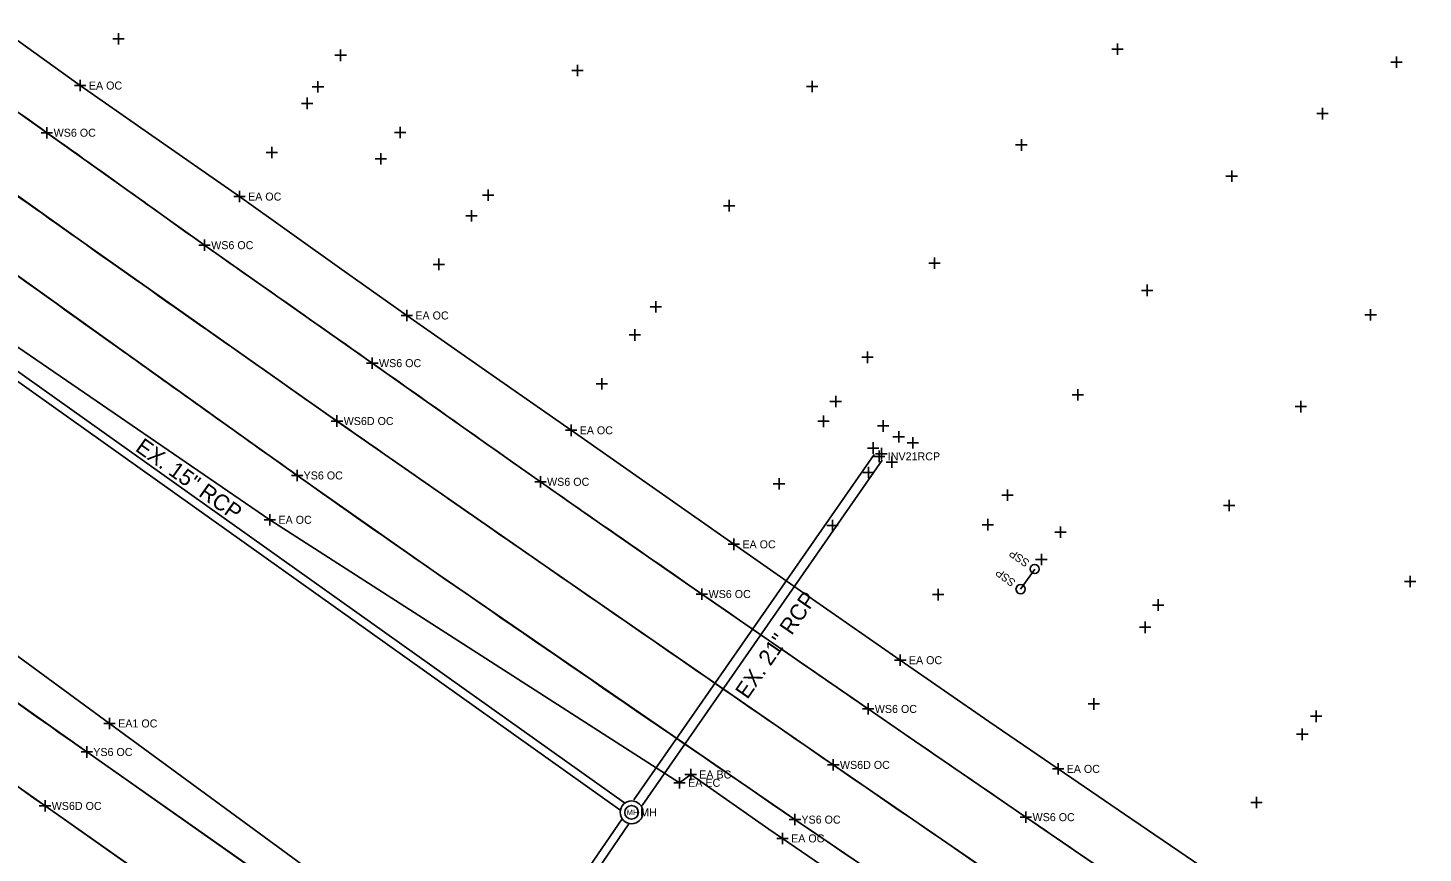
# Model space of a CAD drawing. Extents: x 1324236 to 1326110, y 459090 to 460782.
# Drawn here: x 1325338.7 to 1325582.8, y 459844.3 to 459988.7 of the extents above; entities that cross this region are included whole.
import ezdxf

# ---------------------------------------------------------------- set-up
doc = ezdxf.new("R2010")
doc.units = 0
for name, color, linetype in [('BD_X_Canopy', 7, 'Continuous'), ('DR_X_Ditch', 7, 'Continuous'), ('DT_X_Contour_Minor', 7, 'Continuous'), ('DT_X_Void', 7, 'Continuous'), ('DV_X_Property_Line', 7, 'Continuous'), ('LT_X_Poles', 7, 'Continuous'), ('PM_X_Edge_Line', 7, 'Continuous'), ('PM_X_Lane_Line', 7, 'Continuous'), ('PV_X_Shoulder', 7, 'Continuous'), ('RD_X_Concrete_Barrier', 7, 'Continuous'), ('RW_X_CL', 7, 'Continuous'), ('UT_X_Telecom', 7, 'Continuous'), ('VG_X_Flower_Bed', 7, 'Continuous')]:
    doc.layers.add(name, color=color, linetype=linetype)

msp = doc.modelspace()

# ---------------------------------------------------------------- linework, layer by layer
at = {"layer": 'BD_X_Canopy'}
for points in [[(1325307.55, 459980.26), (1325347.49, 459951.8), (1325347.49, 459951.8), (1325392.78, 459919.94), (1325392.78, 459919.94), (1325429.21, 459894.59), (1325429.21, 459894.59), (1325479.6, 459859.78), (1325479.6, 459859.78), (1325541.3, 459817.45), (1325541.3, 459817.45), (1325560.23, 459804.67), (1325560.23, 459804.67), (1325560.79, 459804.3), (1325560.79, 459804.3), (1325643.88, 459749.04)], [(1325314.22, 459871.98), (1325341.7, 459852.6), (1325341.7, 459852.6), (1325425.03, 459793.93), (1325425.21, 459793.8), (1325425.21, 459793.8), (1325434.79, 459787.27), (1325434.79, 459787.27), (1325453.51, 459774.61), (1325453.51, 459774.61), (1325458.22, 459771.4), (1325458.22, 459771.4), (1325510.42, 459735.74), (1325510.42, 459735.74), (1325543.06, 459713.54), (1325543.06, 459713.54), (1325597.13, 459676.97)]]:
    msp.add_lwpolyline(points, dxfattribs=at)
at = {"layer": 'DR_X_Ditch'}
for points in [[(1325105.01, 460038.08), (1325127.7, 460021.23), (1325155.6, 460000.72), (1325182.42, 459981.06), (1325210.57, 459960.69), (1325238.63, 459940.35), (1325308.7, 459890.5), (1325308.7, 459890.5), (1325349.01, 459862.04), (1325349.01, 459862.04), (1325431.77, 459803.91), (1325432.23, 459803.59), (1325432.23, 459803.59), (1325448.95, 459791.99), (1325448.95, 459791.99), (1325460.04, 459784.34), (1325460.04, 459784.34), (1325460.31, 459784.16), (1325460.31, 459784.16), (1325516.92, 459745.67), (1325550.1, 459723.2), (1325550.1, 459723.2), (1325604.67, 459686.51)], [(1325325.76, 459981.93), (1325342.04, 459970.38), (1325342.04, 459970.38), (1325359.25, 459958.09), (1325359.25, 459958.09), (1325369.61, 459950.71), (1325369.61, 459950.71), (1325379.88, 459943.47), (1325379.88, 459943.47), (1325398.96, 459930.07), (1325398.96, 459930.07), (1325417.95, 459916.66), (1325417.95, 459916.66), (1325428.37, 459909.31), (1325428.37, 459909.31), (1325436.63, 459903.54), (1325436.63, 459903.54), (1325456.61, 459889.67), (1325456.61, 459889.67), (1325475.78, 459876.41), (1325475.78, 459876.41), (1325485.69, 459869.57), (1325485.69, 459869.57), (1325493.79, 459864.01), (1325493.79, 459864.01), (1325513.29, 459850.64), (1325513.29, 459850.64), (1325530.31, 459839)], [(1325300.69, 459971.28), (1325355.76, 459931.86), (1325355.76, 459931.86), (1325385.82, 459910.42), (1325385.82, 459910.42), (1325409.62, 459893.72), (1325409.62, 459893.72), (1325472.9, 459850.21), (1325472.9, 459850.21), (1325473.97, 459849.48), (1325473.97, 459849.48), (1325555.27, 459794.26), (1325555.27, 459794.26), (1325588.76, 459771.64)]]:
    msp.add_lwpolyline(points, dxfattribs=at)
at = {"layer": 'DT_X_Contour_Minor'}
msp.add_line((1325514.84, 459894.05), (1325512.36, 459890.53), dxfattribs=at)
for centre in [(1325514.84, 459894.05), (1325512.36, 459890.53)]:
    msp.add_circle(centre, 0.8, dxfattribs=at)
at = {"layer": 'DV_X_Property_Line'}
for p, q in [((1325346.87, 459978.64), (1325348.87, 459978.64)), ((1325347.87, 459977.64), (1325347.87, 459979.64)), ((1325374.72, 459959.21), (1325376.72, 459959.21)), ((1325375.72, 459958.21), (1325375.72, 459960.21)), ((1325404.99, 459937.41), (1325404.99, 459939.41)), ((1325403.99, 459938.41), (1325405.99, 459938.41)), ((1325432.73, 459918.32), (1325434.73, 459918.32)), ((1325433.73, 459917.32), (1325433.73, 459919.32)), ((1325486.63, 459913.76), (1325488.63, 459913.76)), ((1325487.63, 459912.76), (1325487.63, 459914.76)), ((1325380.04, 459902.66), (1325382.04, 459902.66)), ((1325381.04, 459901.66), (1325381.04, 459903.66)), ((1325461.2, 459898.37), (1325463.2, 459898.37)), ((1325462.2, 459897.37), (1325462.2, 459899.37)), ((1325491.32, 459877.1), (1325491.32, 459879.1)), ((1325490.32, 459878.1), (1325492.32, 459878.1)), ((1325352, 459867.03), (1325354, 459867.03)), ((1325353, 459866.03), (1325353, 459868.03)), ((1325454.65, 459857.1), (1325454.65, 459859.1)), ((1325517.92, 459859.08), (1325519.92, 459859.08)), ((1325518.92, 459858.08), (1325518.92, 459860.08)), ((1325451.71, 459856.65), (1325453.71, 459856.65)), ((1325452.71, 459855.65), (1325452.71, 459857.65)), ((1325453.65, 459858.1), (1325455.65, 459858.1)), ((1325469.72, 459846.92), (1325471.72, 459846.92)), ((1325470.72, 459845.92), (1325470.72, 459847.92))]:
    msp.add_line(p, q, dxfattribs=at)
at = {"layer": 'LT_X_Poles'}
for points in [[(1325105.01, 460038.08), (1325127.7, 460021.23), (1325155.6, 460000.72), (1325182.42, 459981.06), (1325210.57, 459960.69), (1325238.63, 459940.35), (1325308.7, 459890.5), (1325308.7, 459890.5), (1325349.01, 459862.04), (1325349.01, 459862.04), (1325431.77, 459803.91), (1325432.23, 459803.59), (1325432.23, 459803.59), (1325448.95, 459791.99), (1325448.95, 459791.99), (1325460.04, 459784.34), (1325460.04, 459784.34), (1325460.31, 459784.16), (1325460.31, 459784.16), (1325516.92, 459745.67), (1325550.1, 459723.2), (1325550.1, 459723.2), (1325604.67, 459686.51)], [(1325325.76, 459981.93), (1325342.04, 459970.38), (1325342.04, 459970.38), (1325359.25, 459958.09), (1325359.25, 459958.09), (1325369.61, 459950.71), (1325369.61, 459950.71), (1325379.88, 459943.47), (1325379.88, 459943.47), (1325398.96, 459930.07), (1325398.96, 459930.07), (1325417.95, 459916.66), (1325417.95, 459916.66), (1325428.37, 459909.31), (1325428.37, 459909.31), (1325436.63, 459903.54), (1325436.63, 459903.54), (1325456.61, 459889.67), (1325456.61, 459889.67), (1325475.78, 459876.41), (1325475.78, 459876.41), (1325485.69, 459869.57), (1325485.69, 459869.57), (1325493.79, 459864.01), (1325493.79, 459864.01), (1325513.29, 459850.64), (1325513.29, 459850.64), (1325530.31, 459839)], [(1325300.69, 459971.28), (1325355.76, 459931.86), (1325355.76, 459931.86), (1325385.82, 459910.42), (1325385.82, 459910.42), (1325409.62, 459893.72), (1325409.62, 459893.72), (1325472.9, 459850.21), (1325472.9, 459850.21), (1325473.97, 459849.48), (1325473.97, 459849.48), (1325555.27, 459794.26), (1325555.27, 459794.26), (1325588.76, 459771.64)]]:
    msp.add_lwpolyline(points, dxfattribs=at)
at = {"layer": 'PM_X_Edge_Line'}
msp.add_line((1325349.01, 459862.04), (1325431.77, 459803.91), dxfattribs=at)
for centre, radius, start, end in [((1320897.41, 453722.4), 7667.6, 54.573065, 54.7222), ((1359807.69, 508122.03), 59238.74, 234.3729031, 234.4384039), ((1322328.44, 455734.05), 5198.88, 54.33999, 54.57307), ((1326454.8, 461484.96), 1879.25, 234.33999, 234.72766), ((1327143.49, 462458.62), 3071.86, 234.72766, 234.96209), ((1319309.87, 451286.8), 10572.75, 54.835724, 54.962087), ((1335598.98, 474259.73), 17612.82, 234.438404, 234.55853), ((1319358.11, 451355.28), 10488.99, 54.708748, 54.835724), ((1327240.34, 462491.35), 3154.39, 234.70875, 234.94029), ((1326622.12, 461647.4), 2132.02, 234.55853, 235.34003), ((1326755.43, 461800.36), 2310.23, 234.94029, 235.19036), ((1333109, 470938.66), 13440.2, 235.190365, 235.294044), ((1333863.99, 472121.62), 14866, 235.340033, 235.635989), ((1331446.62, 468542.61), 10608.16, 234.647573, 234.914102), ((1339960.11, 480830.74), 25473.12, 235.294044, 235.346473), ((1329342.62, 465470.52), 6800.47, 235.346472, 235.447942), ((1328838.77, 464738.85), 5912.1, 235.447942, 235.543122), ((1344880.98, 488118.08), 34265.95, 235.543123, 235.582658), ((1325708.58, 460194.88), 417.55, 235.636, 235.8141), ((2669726.67, 2438908.34), 2392423.31, 235.81414878, 235.81650239), ((1331310.67, 468312), 10256.91, 235.582658, 235.697812)]:
    msp.add_arc(centre, radius, start, end, dxfattribs=at)
at = {"layer": 'PM_X_Lane_Line'}
msp.add_line((1325341.7, 459852.6), (1325425.03, 459793.93), dxfattribs=at)
for centre, radius, start, end in [((1329666.99, 466055.14), 7477.22, 234.336201, 234.711945), ((1330856.24, 467735.53), 9535.87, 234.711945, 235.044668), ((1331611.15, 468815.44), 10853.48, 235.044668, 235.278976), ((1337198.47, 476878.24), 20663.01, 235.278976, 235.44879), ((1344588.79, 487185.54), 33429.63, 234.790231, 234.847873), ((1337603.44, 477466.35), 21377.07, 235.44879, 235.649353)]:
    msp.add_arc(centre, radius, start, end, dxfattribs=at)
at = {"layer": 'PV_X_Shoulder'}
for points in [[(1325335.4, 459987.63), (1325347.87, 459978.64), (1325347.87, 459978.64), (1325359.81, 459970.28), (1325359.81, 459970.28), (1325375.72, 459959.21), (1325375.72, 459959.21), (1325393.63, 459946.46), (1325393.63, 459946.46), (1325404.99, 459938.41), (1325404.99, 459938.41), (1325419.36, 459928.36), (1325419.36, 459928.36), (1325433.73, 459918.32), (1325433.73, 459918.32), (1325447.96, 459908.35), (1325447.96, 459908.35), (1325462.2, 459898.37), (1325462.2, 459898.37), (1325473.84, 459890.25), (1325473.84, 459890.25), (1325491.32, 459878.1), (1325491.32, 459878.1), (1325506.79, 459867.4), (1325506.79, 459867.4), (1325518.92, 459859.08), (1325518.92, 459859.08), (1325530.55, 459851.15), (1325530.55, 459851.15), (1325545.38, 459841.06)], [(1325331.71, 459936.44), (1325381.04, 459902.66), (1325381.04, 459902.66), (1325452.71, 459856.65), (1325454.65, 459858.1), (1325468.35, 459848.56), (1325468.35, 459848.56), (1325470.72, 459846.92), (1325470.72, 459846.92), (1325547.09, 459794.65), (1325547.09, 459794.65), (1325552.23, 459791.15), (1325552.23, 459791.15), (1325553.3, 459790.42), (1325553.3, 459790.42), (1325634.91, 459735.61)], [(1325325.35, 459887.25), (1325353, 459867.03), (1325353, 459867.03), (1325429.79, 459810.77), (1325429.79, 459810.77), (1325434.67, 459807.23), (1325434.67, 459807.23), (1325441.94, 459802.11), (1325441.94, 459802.11), (1325462.47, 459788.01), (1325462.47, 459788.01), (1325463.09, 459787.58), (1325463.09, 459787.58), (1325519.68, 459749.09), (1325552.6, 459726.78), (1325552.6, 459726.78), (1325606.98, 459690.17)]]:
    msp.add_lwpolyline(points, dxfattribs=at)
at = {"layer": 'RD_X_Concrete_Barrier'}
for radius in [2, 1.2]:
    msp.add_circle((1325444.31, 459851.48), radius, dxfattribs=at)
at = {"layer": 'RW_X_CL'}
for p, q in [((1325353.57, 459986.8), (1325355.57, 459986.8)), ((1325354.57, 459985.8), (1325354.57, 459987.8)), ((1325529.32, 459984.02), (1325529.32, 459986.02)), ((1325392.42, 459983.93), (1325394.42, 459983.93)), ((1325393.42, 459982.93), (1325393.42, 459984.93)), ((1325528.32, 459985.02), (1325530.32, 459985.02)), ((1325578.12, 459981.73), (1325578.12, 459983.73)), ((1325433.86, 459981.25), (1325435.86, 459981.25)), ((1325434.86, 459980.25), (1325434.86, 459982.25)), ((1325577.12, 459982.73), (1325579.12, 459982.73)), ((1325388.45, 459978.43), (1325390.45, 459978.43)), ((1325389.45, 459977.43), (1325389.45, 459979.43)), ((1325474.89, 459978.47), (1325476.89, 459978.47)), ((1325475.89, 459977.47), (1325475.89, 459979.47)), ((1325387.56, 459974.52), (1325387.56, 459976.52)), ((1325386.56, 459975.52), (1325388.56, 459975.52)), ((1325564.18, 459973.72), (1325566.18, 459973.72)), ((1325565.18, 459972.72), (1325565.18, 459974.72)), ((1325342.04, 459969.38), (1325342.04, 459971.38)), ((1325403.82, 459969.41), (1325403.82, 459971.41)), ((1325341.04, 459970.38), (1325343.04, 459970.38)), ((1325402.82, 459970.41), (1325404.82, 459970.41)), ((1325512.5, 459967.24), (1325512.5, 459969.24)), ((1325380.38, 459966.91), (1325382.38, 459966.91)), ((1325381.38, 459965.91), (1325381.38, 459967.91)), ((1325400.44, 459964.82), (1325400.44, 459966.82)), ((1325511.5, 459968.24), (1325513.5, 459968.24)), ((1325399.44, 459965.82), (1325401.44, 459965.82)), ((1325549.29, 459961.77), (1325549.29, 459963.77)), ((1325548.29, 459962.77), (1325550.29, 459962.77)), ((1325418.24, 459959.44), (1325420.24, 459959.44)), ((1325419.24, 459958.44), (1325419.24, 459960.44)), ((1325416.32, 459954.84), (1325416.32, 459956.84)), ((1325460.38, 459957.62), (1325462.38, 459957.62)), ((1325461.38, 459956.62), (1325461.38, 459958.62)), ((1325415.32, 459955.84), (1325417.32, 459955.84)), ((1325369.61, 459949.71), (1325369.61, 459951.71)), ((1325368.61, 459950.71), (1325370.61, 459950.71)), ((1325409.58, 459947.35), (1325411.58, 459947.35)), ((1325410.58, 459946.35), (1325410.58, 459948.35)), ((1325496.32, 459947.57), (1325498.32, 459947.57)), ((1325497.32, 459946.57), (1325497.32, 459948.57)), ((1325533.52, 459942.8), (1325535.52, 459942.8)), ((1325534.52, 459941.8), (1325534.52, 459943.8)), ((1325447.55, 459939.92), (1325449.55, 459939.92)), ((1325448.55, 459938.92), (1325448.55, 459940.92)), ((1325573.6, 459937.54), (1325573.6, 459939.54)), ((1325572.6, 459938.54), (1325574.6, 459938.54)), ((1325443.89, 459935), (1325445.89, 459935)), ((1325444.89, 459934), (1325444.89, 459936)), ((1325485.6, 459930.09), (1325485.6, 459932.09)), ((1325397.96, 459930.07), (1325399.96, 459930.07)), ((1325398.96, 459929.07), (1325398.96, 459931.07)), ((1325484.6, 459931.09), (1325486.6, 459931.09)), ((1325439.1, 459925.46), (1325439.1, 459927.46)), ((1325438.1, 459926.46), (1325440.1, 459926.46)), ((1325522.38, 459923.51), (1325522.38, 459925.51)), ((1325479.02, 459923.37), (1325481.02, 459923.37)), ((1325480.02, 459922.37), (1325480.02, 459924.37)), ((1325521.38, 459924.51), (1325523.38, 459924.51)), ((1325560.38, 459922.46), (1325562.38, 459922.46)), ((1325561.38, 459921.46), (1325561.38, 459923.46)), ((1325391.78, 459919.94), (1325393.78, 459919.94)), ((1325392.78, 459918.94), (1325392.78, 459920.94)), ((1325476.88, 459919.89), (1325478.88, 459919.89)), ((1325477.88, 459918.89), (1325477.88, 459920.89)), ((1325488.34, 459918.08), (1325488.34, 459920.08)), ((1325487.34, 459919.08), (1325489.34, 459919.08)), ((1325491.04, 459916.19), (1325491.04, 459918.19)), ((1325485.57, 459915.22), (1325487.57, 459915.22)), ((1325486.57, 459914.22), (1325486.57, 459916.22)), ((1325488.01, 459913.23), (1325488.01, 459915.23)), ((1325490.04, 459917.19), (1325492.04, 459917.19)), ((1325492.51, 459916.12), (1325494.51, 459916.12)), ((1325493.51, 459915.12), (1325493.51, 459917.12)), ((1325487.01, 459914.23), (1325489.01, 459914.23)), ((1325488.85, 459912.74), (1325490.85, 459912.74)), ((1325489.85, 459911.74), (1325489.85, 459913.74)), ((1325384.82, 459910.42), (1325386.82, 459910.42)), ((1325385.82, 459909.42), (1325385.82, 459911.42)), ((1325428.37, 459908.31), (1325428.37, 459910.31)), ((1325470.11, 459907.95), (1325470.11, 459909.95)), ((1325484.77, 459910.92), (1325486.77, 459910.92)), ((1325485.77, 459909.92), (1325485.77, 459911.92)), ((1325427.37, 459909.31), (1325429.37, 459909.31)), ((1325469.11, 459908.95), (1325471.11, 459908.95)), ((1325510.08, 459905.97), (1325510.08, 459907.97)), ((1325509.08, 459906.97), (1325511.08, 459906.97)), ((1325547.86, 459905.18), (1325549.86, 459905.18)), ((1325548.86, 459904.18), (1325548.86, 459906.18)), ((1325479.45, 459900.67), (1325479.45, 459902.67)), ((1325506.62, 459900.81), (1325506.62, 459902.81)), ((1325478.45, 459901.67), (1325480.45, 459901.67)), ((1325505.62, 459901.81), (1325507.62, 459901.81)), ((1325518.34, 459900.49), (1325520.34, 459900.49)), ((1325519.34, 459899.49), (1325519.34, 459901.49)), ((1325515, 459895.71), (1325517, 459895.71)), ((1325516, 459894.71), (1325516, 459896.71)), ((1325580.52, 459890.87), (1325580.52, 459892.87)), ((1325456.61, 459888.67), (1325456.61, 459890.67)), ((1325497.95, 459888.57), (1325497.95, 459890.57)), ((1325579.52, 459891.87), (1325581.52, 459891.87)), ((1325455.61, 459889.67), (1325457.61, 459889.67)), ((1325496.95, 459889.57), (1325498.95, 459889.57)), ((1325536.44, 459886.75), (1325536.44, 459888.75)), ((1325535.44, 459887.75), (1325537.44, 459887.75)), ((1325533.17, 459883.85), (1325535.17, 459883.85)), ((1325534.17, 459882.85), (1325534.17, 459884.85)), ((1325525.19, 459869.44), (1325525.19, 459871.44)), ((1325484.69, 459869.57), (1325486.69, 459869.57)), ((1325485.69, 459868.57), (1325485.69, 459870.57)), ((1325524.19, 459870.44), (1325526.19, 459870.44)), ((1325564.08, 459867.28), (1325564.08, 459869.28)), ((1325561.65, 459864.13), (1325561.65, 459866.13)), ((1325563.08, 459868.28), (1325565.08, 459868.28)), ((1325560.65, 459865.13), (1325562.65, 459865.13)), ((1325348.01, 459862.04), (1325350.01, 459862.04)), ((1325349.01, 459861.04), (1325349.01, 459863.04)), ((1325478.6, 459859.78), (1325480.6, 459859.78)), ((1325479.6, 459858.78), (1325479.6, 459860.78)), ((1325553.63, 459852.19), (1325553.63, 459854.19)), ((1325340.7, 459852.6), (1325342.7, 459852.6)), ((1325341.7, 459851.6), (1325341.7, 459853.6)), ((1325513.29, 459849.64), (1325513.29, 459851.64)), ((1325552.63, 459853.19), (1325554.63, 459853.19)), ((1325471.9, 459850.21), (1325473.9, 459850.21)), ((1325472.9, 459849.21), (1325472.9, 459851.21)), ((1325512.29, 459850.64), (1325514.29, 459850.64))]:
    msp.add_line(p, q, dxfattribs=at)
at = {"layer": 'VG_X_Flower_Bed'}
for p, q in [((1325442.28, 459851.94), (1325181.98, 460037.04)), ((1325443.07, 459853.12), (1325182.75, 460038.25)), ((1325486.73, 459914.09), (1325444.71, 459853.69)), ((1325488.16, 459913.09), (1325446.14, 459852.69)), ((1325388.22, 459770.57), (1325442.64, 459850.35)), ((1325443.86, 459849.49), (1325389.43, 459769.68))]:
    msp.add_line(p, q, dxfattribs=at)

# ---------------------------------------------------------------- texts
at = {"layer": 'DT_X_Contour_Minor'}
for rotation, p in [(145.1342, (1325514.05, 459895.45)), (142.8498, (1325511.63, 459891.96))]:
    msp.add_text('SSP', height=1.4, rotation=rotation, dxfattribs=at).set_placement(p)
at = {"layer": 'DT_X_Void'}
msp.add_text('MH', height=1.4, dxfattribs=at).set_placement((1325445.81, 459850.78))
at = {"layer": 'DV_X_Property_Line'}
for s, p in [('EA OC', (1325349.37, 459977.94)), ('EA OC', (1325377.22, 459958.51)), ('EA OC', (1325406.49, 459937.71)), ('EA OC', (1325435.23, 459917.62)), ('INV21RCP', (1325489.13, 459913.06)), ('EA OC', (1325382.54, 459901.96)), ('EA OC', (1325463.7, 459897.67)), ('EA OC', (1325492.82, 459877.4)), ('EA1 OC', (1325354.5, 459866.33)), ('EA BC', (1325456.15, 459857.4)), ('EA OC', (1325520.42, 459858.38)), ('EA EC', (1325454.21, 459855.95)), ('EA OC', (1325472.22, 459846.22))]:
    msp.add_text(s, height=1.4, dxfattribs=at).set_placement(p)
at = {"layer": 'RD_X_Concrete_Barrier'}
msp.add_text('MH', height=0.96, dxfattribs=at).set_placement((1325443.44, 459851))
at = {"layer": 'RW_X_CL'}
for s, p in [('WS6 OC', (1325343.21, 459969.68)), ('WS6 OC', (1325370.77, 459950.01)), ('WS6 OC', (1325400.13, 459929.37)), ('WS6D OC', (1325393.95, 459919.24)), ('YS6 OC', (1325386.94, 459909.72)), ('WS6 OC', (1325429.53, 459908.61)), ('WS6 OC', (1325457.78, 459888.97)), ('WS6 OC', (1325486.86, 459868.87)), ('YS6 OC', (1325350.14, 459861.34)), ('WS6D OC', (1325480.76, 459859.08)), ('WS6D OC', (1325342.87, 459851.9)), ('WS6 OC', (1325514.46, 459849.94)), ('YS6 OC', (1325474.02, 459849.51))]:
    msp.add_text(s, height=1.4, dxfattribs=at).set_placement(p)
at = {"layer": 'UT_X_Telecom'}
for s, rotation, p in [('EX. 15" RCP', 324.5286, (1325357.33, 459914.85)), ('EX. 21" RCP', 55.3441, (1325464.57, 459871.13))]:
    msp.add_text(s, height=2.8, rotation=rotation, dxfattribs=at).set_placement(p)

doc.saveas('drawing.dxf')
